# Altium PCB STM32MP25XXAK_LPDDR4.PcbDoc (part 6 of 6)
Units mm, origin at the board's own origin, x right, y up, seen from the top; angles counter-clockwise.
Board outline 120 x 79.6 mm, 4 copper layers (Top Layer, Signal Layer 1, Signal Layer 2, Bottom Layer), stack 1.614 mm thick; 190 components, 143 nets, 1208 pads, 757 vias.
Unrouted connection lines stored in the file: 3.
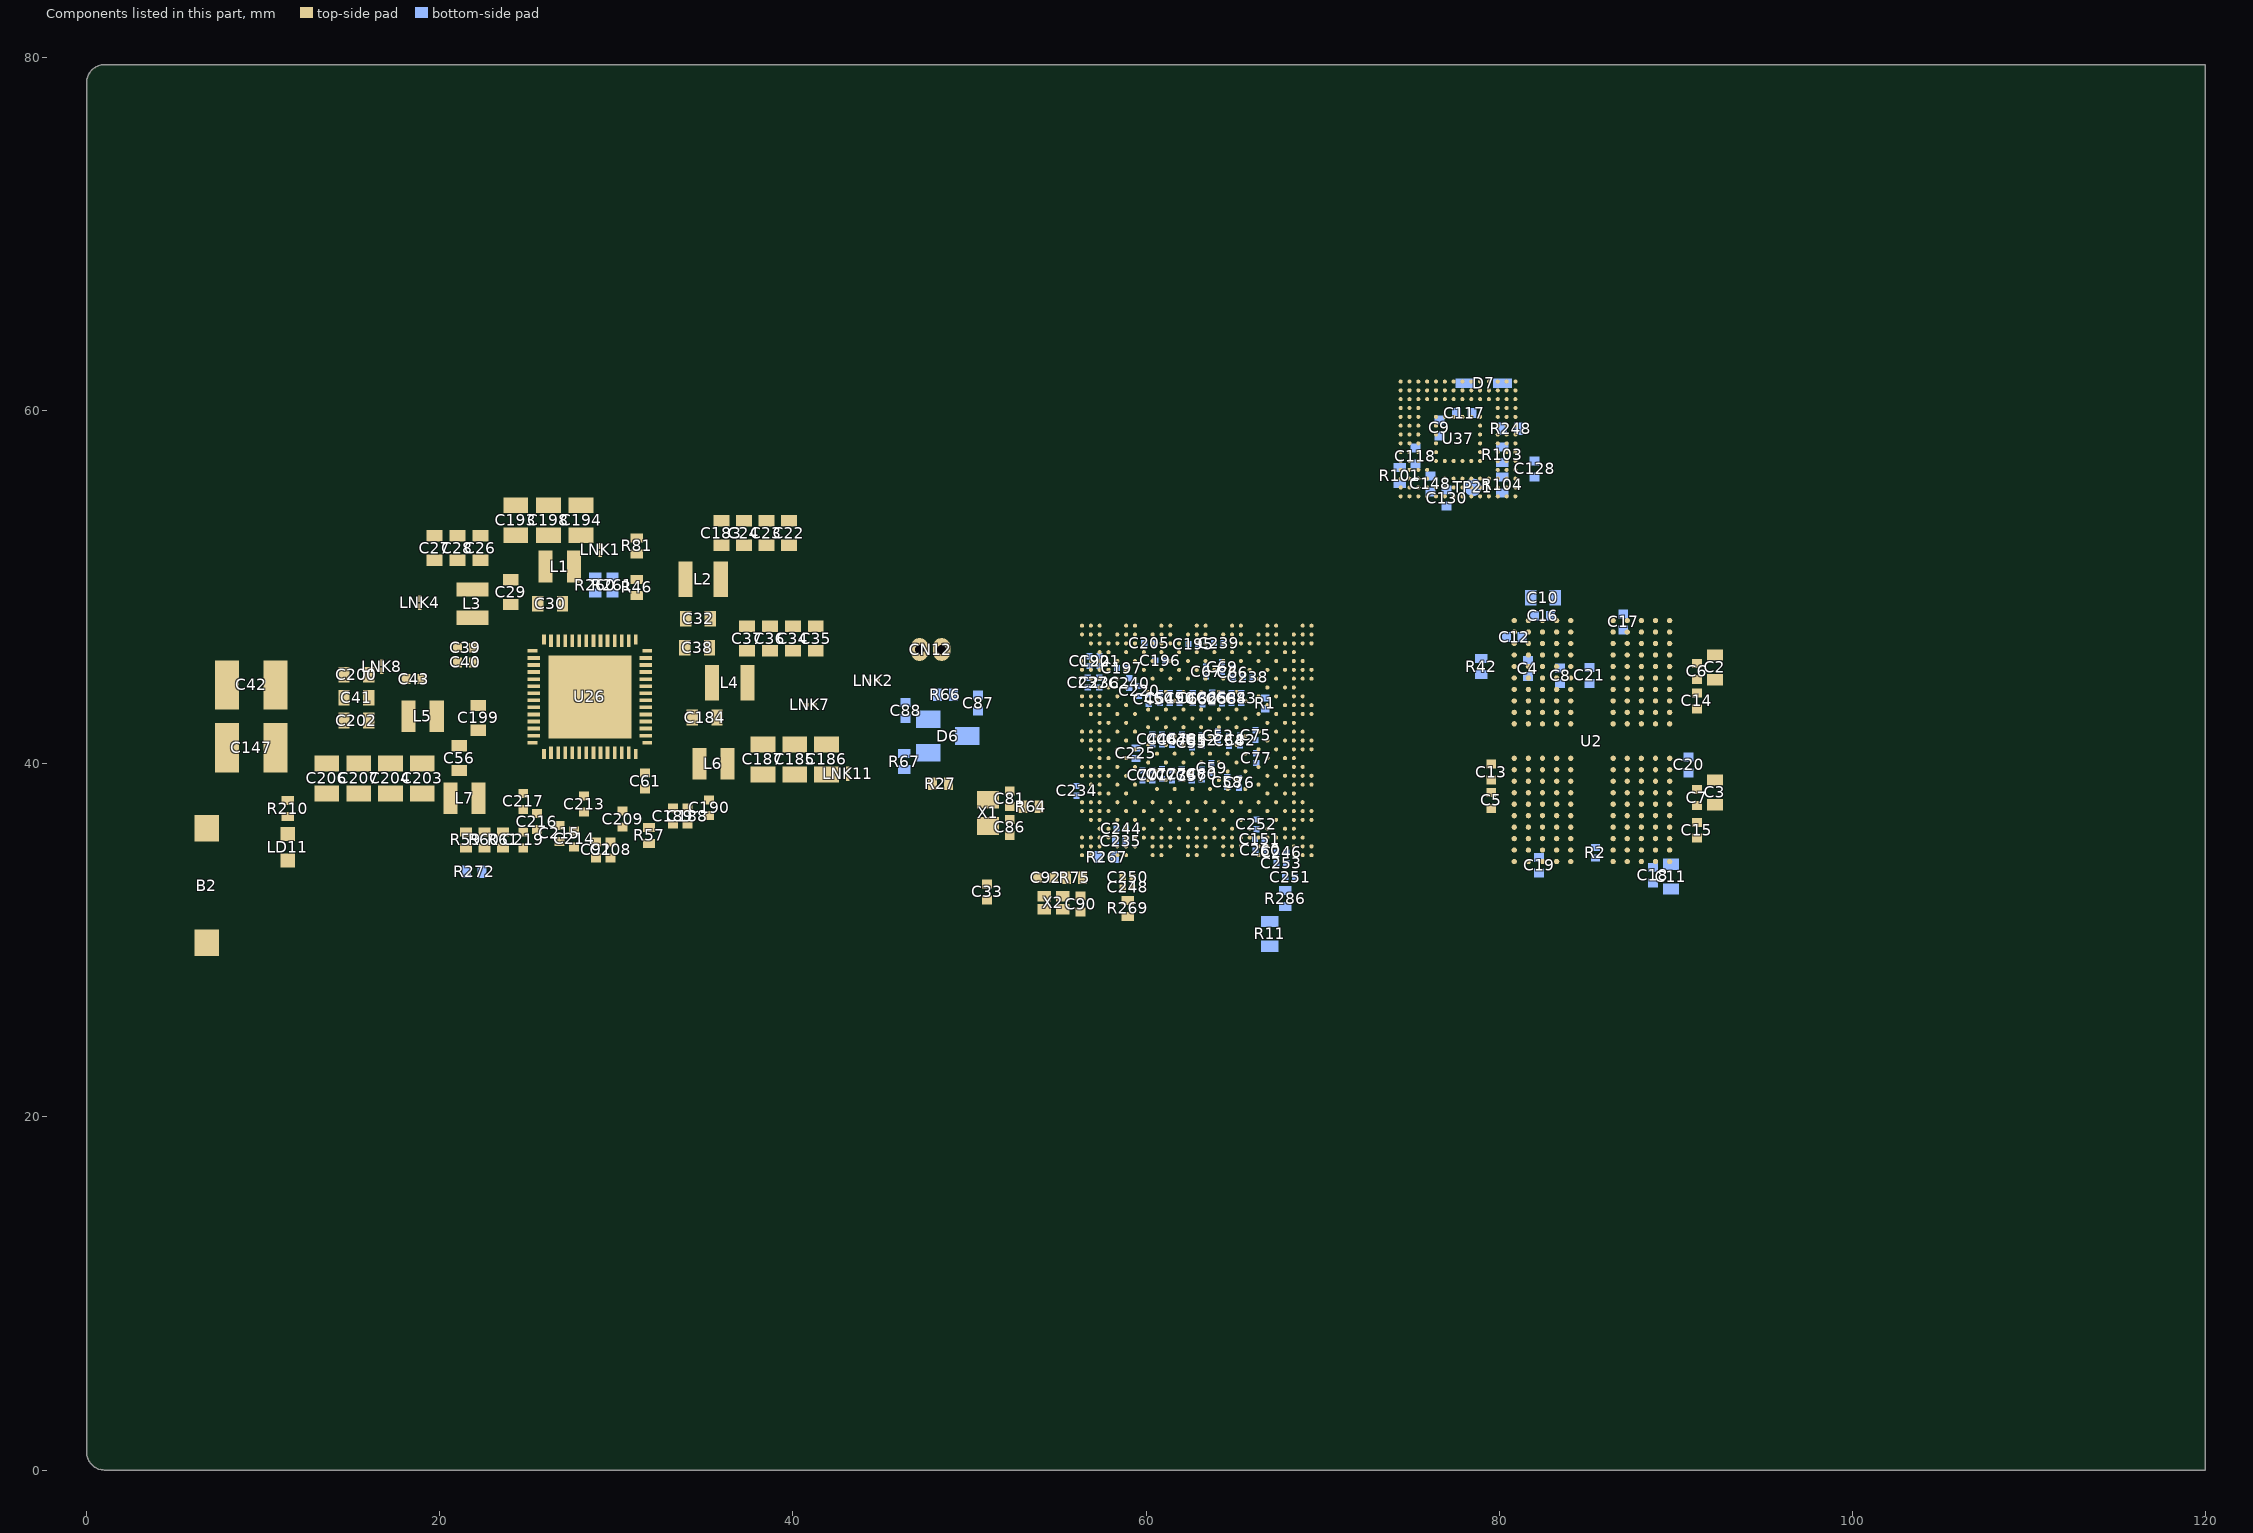
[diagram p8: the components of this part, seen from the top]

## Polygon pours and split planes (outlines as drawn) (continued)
5V_STLK on Signal Layer 2 "5V_STLK_L03_P051" (solid, pour order 51): 11.875,50.635 37.435,50.635 37.475,50.595 37.475,31.99 14.15,31.99 11.911,34.229
GND on Top Layer "GND_L01_P053" (solid, remove dead copper, pour order 53): 0,79.797 120,79.797 120,0.197 0,0.197
5V_STLK on Top Layer "5V_VIN" (solid, pour order 17): 22.51,43.62 23.167,43.62 23.35,43.803 23.35,43.463 22.867,42.98 22.51,42.98
VDDCPU on Top Layer "I_SENS_VDDCPU_P" (solid, pour order 18): 17.812,51.845 17.812,49.998 18.335,49.475 22.75,49.475 22.745,49.48 22.745,51.845
VDDCORE on Top Layer "I_SENS_VDDCORE_P" (solid, pour order 19): 41.007,52.695 43.889,49.813 43.889,43.586 43.894,43.581 42.44,43.581 41.895,44.126 41.895,48.827 41.522,49.2 39.875,49.2 35.515,49.2 35.505,52.695
VDDGPU on Top Layer "I_SENS_VDDGPU_P" (solid, pour order 20): 41.603,43.6 41.745,43.742 41.745,46.72 37.025,46.72 37.025,43.6
VDDIO on Top Layer "VDDIO" (solid, pour order 22): 30.995,46.77 30.995,48.568 31.53,49.103 31.712,49.103 32.15,48.664 32.15,48.123 31.45,47.423 31.45,46.77
3V3 on Top Layer "3V3" (solid, pour order 23): 12.887,36.548 13.062,36.373 19.41,36.373 20.712,37.675 20.712,38.523 13.088,38.523 12.887,38.323
NetL6_1 on Top Layer "NetL13_1" (solid, pour order 25): 33.375,41.863 33.838,41.4 35.1,41.4 35.1,39.1 35.098,39.098 33.801,39.098 33.801,40.722 33.375,41.148
GND on Signal Layer 1 "GND_L02_P000" (solid, remove dead copper, pour order 0): 0,79.6 120,79.6 120,0 0,0
GND on Bottom Layer "GND_L04_P055" (solid, remove dead copper, pour order 55): 0,79.6 120,79.6 120,0 0,0

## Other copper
Top Layer:
  rectangle net VDD2_DDR: 15.655,41.8 18.625,43.6
  region net NetL1_1: 27.572,49.875 ccw(c27.269,49.883) 27.478,50.102 27.455,50.125 27.455,50.187 27.526,50.194 ccw(c27.525,50.194) 27.525,50.195 27.675,50.075
  region net GND: 32.225,44 32.15,43.925 32.072,43.925 cw(c32.072,43.798) 32.162,43.888 32.188,43.862 ccw(c32.278,43.952) 32.278,43.825 32.947,43.825 cw(c32.947,43.698) 33.037,43.788 33.1,43.725 33.229,43.854 cw(c33.28,43.803) 33.28,43.875
  region net 5V_STLK: 33.605,47.78 33.43,47.672 ccw(c33.563,47.473) 33.394,47.642 33.353,47.601 ccw(c33.613,47.342) 33.246,47.342 33.246,47.326 ccw(c33.601,47.326) 33.35,47.075 33.35,45.539 33.349,45.538 33.347,45.551 32.876,45.08 32.27,45.08 32.27,45.345 32.506,45.345 32.98,45.819 32.98,48.347 33.308,48.67 34.325,48.67 34.325,47.78
  region net 5V_STLK: 25.23,48.524 25.131,48.425 24.775,48.425 cw(c24.775,48.775) 24.425,48.775 24.425,48.825 23.7,48.825 ccw(c23.7,48.75) 23.625,48.75 23.625,48.4 ccw(c23.827,48.397) 23.825,48.195 26.45,48.195 26.85,47.8 27.112,47.8 26.391,48.521 26.125,48.525
  region net GND: 24.9,47.685 24.807,47.685 ccw(c24.807,47.584) 24.735,47.655 24.455,47.375 ccw(c24.526,47.303) 24.425,47.303 24.425,46.975 24.925,46.975 cw(c25.323,46.982) 25.315,47.38 25.575,47.375 ccw(c25.575,47.423) 25.609,47.389 25.705,47.485
  pour cut-out: 56.125,47.825 69.49,47.825 69.49,34.475 69.524,34.441 56.137,34.441
  pour cut-out: 67.469,46.428 67.537,46.496 69.625,46.496 74.724,51.594 87.59,51.594 90.709,48.476 90.709,33.404 86.764,29.459 74.76,29.459 67.404,36.815
  pour cut-out: 74.075,62 81.35,62 81.35,54.798 74.075,54.798
  region net GND: 39,41.298 39,42.651 37.6,42.651 37.6,41.298
  region net GND: 40.8,41.298 40.8,42.651 39.4,42.651 39.4,41.298
  region net GND: 42.6,41.298 42.6,42.651 41.2,42.651 41.2,41.298
  region net GND: 36.502,42.375 36.307,42.18 36,42.18 36,43.07 36.475,43.07 36.67,42.875 36.67,42.375
  region net GND: 36.325,47.975 36.13,47.78 35.275,47.78 35.275,48.67 36.13,48.67 36.325,48.475
  region net GND: 24.275,51.373 24.47,51.178 24.47,50.723 23.58,50.723 23.58,51.178 23.775,51.373
  region net GND: 36.3,46.325 36.105,46.13 35.25,46.13 35.25,47.02 36.105,47.02 36.3,46.825
  region net GND: 37.65,48.825 37.845,48.63 37.845,47.775 36.955,47.775 36.955,48.63 37.15,48.825
  region net GND: 38.95,48.825 39.145,48.63 39.145,47.775 38.255,47.775 38.255,48.63 38.45,48.825
  region net GND: 40.25,48.825 40.445,48.63 40.445,47.775 39.555,47.775 39.555,48.63 39.75,48.825
  region net GND: 41.55,48.825 41.745,48.63 41.745,47.775 40.855,47.775 40.855,48.63 41.05,48.825
  region net VDDIO: 41.58,38.835 41.58,38.719 41.227,38.366 41.227,37.235 41.58,37.235 42.22,37.235 42.577,37.235 42.577,38.431 42.22,38.788 42.22,39.212 41.58,39.212
  region net 5V_STLK: 20.075,39.948 20.725,39.948 20.725,39.305 20.42,39.305 20.325,39.4 20.075,39.4
  region net GND: 19.025,40.798 19.175,40.648 19.175,40.398 18.3,40.398 18.3,40.823 18.525,41.048 19.025,41.048
  region net GND: 19.025,40.798 18.875,40.648 18.875,40.398 19.7,40.398 19.7,40.873 19.525,41.048 19.025,41.048
  region net GND: 17.225,40.798 17.375,40.648 17.375,40.398 16.5,40.398 16.5,40.823 16.725,41.048 17.225,41.048
  region net GND: 17.225,40.798 17.075,40.648 17.075,40.398 17.9,40.398 17.9,40.873 17.725,41.048 17.225,41.048
  region net GND: 15.425,40.798 15.575,40.648 15.575,40.398 14.7,40.398 14.7,40.823 14.925,41.048 15.425,41.048
  region net GND: 15.425,40.798 15.275,40.648 15.275,40.398 16.1,40.398 16.1,40.873 15.925,41.048 15.425,41.048
  region net GND: 13.625,40.798 13.775,40.648 13.775,40.398 12.9,40.398 12.9,40.823 13.125,41.048 13.625,41.048
  region net GND: 13.625,40.798 13.475,40.648 13.475,40.398 14.3,40.398 14.3,40.873 14.125,41.048 13.625,41.048
  region net GND: 20.075,40.75 20.12,40.705 20.68,40.705 20.725,40.75 20.725,41.345 20.42,41.345 20.325,41.25 20.075,41.25
  region net 5V_STLK: 23.25,43.62 23.25,43.4 22.83,42.98 21.15,42.98 21.15,43.525 21.4,43.525 21.495,43.62
  region net GND: 21.925,40.952 21.73,41.147 21.73,41.602 22.62,41.602 22.62,41.147 22.425,40.952
  region net 5V_STLK: 27.175,49.85 27.27,49.755 27.27,49.45 26.63,49.45 26.63,49.805 26.675,49.85 26.675,50.1 27.175,50.1
  region net GND: 24.6,49.323 24.797,49.52 25.25,49.52 25.25,48.63 24.793,48.63 24.6,48.823
  region net VDD2_DDR: 16.295,45.615 16.295,45.731 16.648,46.084 16.648,47.215 16.295,47.215 15.655,47.215 15.298,47.215 15.298,46.019 15.655,45.662 15.655,45.238 16.295,45.238
  region net GND: 13.6,42.7 13.795,42.895 14.575,42.895 14.575,42.005 13.795,42.005 13.6,42.2
  region net GND: 13.6,44 13.795,44.195 14.575,44.195 14.575,43.305 13.795,43.305 13.6,43.5
  region net GND: 13.6,45.3 13.795,45.495 14.575,45.495 14.575,44.605 13.795,44.605 13.6,44.8
  region net GND: 22.55,53.873 22.745,53.678 22.745,53.223 21.855,53.223 21.855,53.678 22.05,53.873
  region net GND: 21.25,53.873 21.445,53.678 21.445,53.223 20.555,53.223 20.555,53.678 20.75,53.873
  region net GND: 19.95,53.873 20.145,53.678 20.145,53.223 19.255,53.223 19.255,53.678 19.45,53.873
  region net GND: 40.025,54.825 40.22,54.63 40.22,53.775 39.33,53.775 39.33,54.63 39.525,54.825
  region net GND: 38.75,54.825 38.945,54.63 38.945,53.775 38.055,53.775 38.055,54.63 38.25,54.825
  region net GND: 37.475,54.825 37.67,54.63 37.67,53.775 36.78,53.775 36.78,54.63 36.975,54.825
  region net GND: 36.2,54.825 36.395,54.63 36.395,53.775 35.505,53.775 35.505,54.63 35.7,54.825
  region net GND: 24.325,55.425 24.475,55.275 24.475,55.025 23.6,55.025 23.6,55.45 23.825,55.675 24.325,55.675
  region net GND: 24.325,55.425 24.175,55.275 24.175,55.025 25,55.025 25,55.5 24.825,55.675 24.325,55.675
  region net GND: 26.175,55.425 26.025,55.275 26.025,55.025 26.85,55.025 26.85,55.5 26.675,55.675 26.175,55.675
  region net GND: 26.175,55.425 26.325,55.275 26.325,55.025 25.45,55.025 25.45,55.45 25.675,55.675 26.175,55.675
  region net GND: 28.025,55.425 27.875,55.275 27.875,55.025 28.7,55.025 28.7,55.5 28.525,55.675 28.025,55.675
  region net GND: 28.025,55.425 28.175,55.275 28.175,55.025 27.3,55.025 27.3,55.45 27.525,55.675 28.025,55.675
  region net NetL2_1: 33.65,50.225 33.65,49.45 33.515,49.45 32.825,48.76 32.825,46 32.35,45.525 32.025,45.525 32.025,45.675 32.114,45.675 32.27,45.831 32.45,46.011 32.505,46.094 32.525,46.191 32.525,46.742 32.57,46.85 32.57,47.01 32.509,47.157 32.397,47.269 32.27,47.322 32.25,47.325 32.25,51.102 32.598,51.45 33.515,51.45 33.65,51.315 33.65,51.2
  region net NetL4_1: 34.525,45.6 34.525,43.6 35.434,43.6 35.434,45.6
  region net NetL3_1: 22.575,46.975 21.388,48.162 22.488,48.162 22.575,48.075 26.18,48.075 26.42,47.835 24.79,47.835 24.768,47.833 24.748,47.829 24.72,47.82 24.701,47.813 24.675,47.799 24.658,47.788 24.635,47.769 24.341,47.474 24.322,47.452 24.311,47.435 24.302,47.419 24.29,47.39 24.286,47.378 24.281,47.362 24.277,47.342 24.276,47.327 24.274,47.313 24.274,46.975
  region net NetL3_1: 23.783,48.045 23.754,48.048 23.725,48.057 23.651,48.089 23.625,48.103 23.603,48.122 23.547,48.18 23.528,48.203 23.514,48.229 23.488,48.294 23.481,48.316 23.458,48.347 23.433,48.367 23.397,48.391 23.351,48.4 22.575,48.4 22.575,47.263
  region net NetL7_1: 22.875,38.35 22.575,38.05 21.8,38.05 21.8,38.95 22.875,40.02
  region net NetL1_1: 27.995,50.275 27.65,49.93 27.195,50.385 27.195,52.075 27.995,52.075
  region net NetL5_1: 19.425,43.948 19.65,44.173 21.025,44.173 21.025,42.323 20.502,41.8 20.225,41.8 19.425,41.8
  region net 5V_STLK: 34.125,45.25 33.55,44.675 32.875,44.675 32.875,44.85 33.4,45.375
  region net GND: 32.83,44.125 33.28,44.125 33.28,43.825 33.155,43.7 32.98,43.875 32.83,43.875
  region net 5V_STLK: 34.075,41.85 33.977,41.948 33.977,42.625 34.62,42.625 34.62,41.895 34.575,41.85 34.575,41.6 34.075,41.6
  region net 5V_STLK: 34.075,41.875 34.075,42.125 33.175,43.025 33.925,43.025 34.247,42.703
  region net 5V_STLK: 34.195,46.175 34.195,45.32 34.125,45.25 34,45.375 33.4,45.375 33.555,45.53 33.555,46.175
  pour cut-out: 42.6,39.925 37.63,39.925 37.63,40.575 42.6,40.575
  pour cut-out: 12.9,38.773 19.55,38.773 19.55,39.573 12.9,39.573
  region net 5V_STLK: 34.175,49 34.325,48.85 34.325,48.6 33.525,48.6 33.525,48.85 33.675,49 33.675,49.25 34.175,49.25
  region net 5V_STLK: 23.25,49.3 23.295,49.345 23.65,49.345 23.65,48.65 23.4,48.65 23.25,48.8 23,48.8 23,49.3
  region net GND: 31.921,46.656 32.02,46.656 32.049,46.653 32.078,46.644 32.104,46.63 32.127,46.612 32.145,46.589 32.17,46.555 32.17,46.23 32.27,46.23 32.27,46.93 31.921,46.93
  region net 5V_STLK: 27.425,47.725 27.4,47.725 26.63,48.495 26.63,48.825 27.27,48.825 27.27,48.605 27.4,48.475 27.4,47.925
  region net GND: 25.575,47.375 25.24,47.375 25.24,47.385
  pour cut-out: 35.9,41.075 35.1,41.075 35.1,38.975 35.9,38.975
  pour cut-out: 36.955,45.45 35.895,45.45 35.895,43.35 36.955,43.35
  pour cut-out: 35.445,51.25 34.385,51.25 34.385,49.15 35.445,49.15
  pour cut-out: 21.94,39.1 20.88,39.1 20.88,37 21.94,37
  pour cut-out: 27.155,52.225 26.435,52.225 26.435,50.125 27.155,50.125
  pour cut-out: 20.8,49.605 20.8,48.545 22.9,48.545 22.9,49.605
  pour cut-out: 21.5,40.6 19.55,40.6 19.55,40.025 21.5,40.025
  region net 5V_STLK: 22.875,40.9 22.716,40.9 22.689,40.874 22.648,40.842 22.602,40.815 22.554,40.795 22.503,40.782 22.451,40.775 22.425,40.774 21.925,40.774 21.899,40.775 21.847,40.782 21.796,40.795 21.748,40.815 21.702,40.842 21.661,40.874 21.65,40.45 21.65,39.945 21.375,39.945 21.375,39.305 21.83,39.305 22.599,40.074 22.599,40.184 22.603,40.227 22.613,40.27 22.629,40.31 22.652,40.346 22.68,40.379 23.038,40.737
  pour cut-out: 18.495,41.65 19.555,41.65 19.555,43.75 18.495,43.75
  pour cut-out: 35.855,40.875 37.63,40.875 37.63,39.6 36.3,39.6
  region net 5V_STLK: 34.125,47.35 34.275,47.2 34.275,46.95 33.475,46.95 33.475,47.2 33.625,47.35 33.625,47.6 34.125,47.6
Bottom Layer:
  pour cut-out: 66.146,48.032 66.498,48.032 73.987,48.032 76.358,45.662 88.892,45.662 88.892,38.218 85.406,34.732 68.413,34.732 66.15,36.923

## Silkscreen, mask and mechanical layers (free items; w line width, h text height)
Top Overlay:
  text "J" at 27.263,70.56 h15
Drill Drawing:
  drawing of 190 lines, arcs and shapes, not listed
  text "PCB SPECIFICATIONS :" at -27.02,127.275 h3
  text "A.   MATERIAL :" at -27.02,123.275 h3
  text "FR-4" at 11.48,123.275 h3
  text "TG-170" at 27.98,123.275 h3
  text "X  TG-150" at 46.23,123.275 h3
  text "TG-140" at 62.23,123.275 h3
  text "B.   MATERIAL FAMILY :" at -27.02,120.275 h3
  text "N/A" at 11.48,120.275 h3
  text "C.   SOLDERMASK COLOR :" at -27.02,117.275 h3
  text "GREEN" at 11.48,117.275 h3
  text "X  BLUE" at 27.98,117.275 h3
  text "RED" at 46.23,117.275 h3
  text "BLACK" at 62.23,117.275 h3
  text "D.   SILKSCREEN COLOR :" at -27.02,114.275 h3
  text "X  WHITE" at 11.48,114.275 h3
  text "YELLOW" at 27.98,114.275 h3
  text "BLACK" at 46.23,114.275 h3
  text "PCB : TYPE 4" at 187.138,113.471 h3
  text "Layer" at 122.2,111.475 h2
  text "Name" at 130.564,111.475 h2
  text "Material" at 146.732,111.475 h2
  text "Thickness" at 161.266,111.475 h2
  text "Constant" at 173.202,111.475 h2
  text "E.   SURFACE FINISH :" at -27.02,111.275 h3
  text "X  ENIG" at 11.48,111.275 h3
  text "IMMERSION SILVER" at 27.98,111.275 h3
  text "IMMERSION TIN" at 62.23,111.275 h3
  text "HASL" at 11.48,108.275 h3
  text "HASL (PB-FREE)" at 27.98,108.275 h3
  text "GOLDEN FINGER" at 62.23,108.275 h3
  text "ASPECT-RATIO, AXE Z :" at 187.138,107.971 h3
  text "Top Overlay" at 130.564,107.475 h2
  text "F.   IMPEDANCE CONTROL :" at -27.02,105.275 h3
  text "NO" at 11.48,105.275 h3
  text "X  YES" at 27.98,105.275 h3
  text "Top Solder" at 130.564,103.475 h2
  text "Solder Resist" at 146.732,103.475 h2
  text "0.025mm" at 161.266,103.475 h2
  text "3.5" at 173.202,103.475 h2
  text "G.   THROUGH VIA :" at -27.02,102.275 h3
  text "PLUG THE VIAS WHICH ARE COVERED WITH SOLDERMASK ONE OR TWO SIDE." at 11.48,102.275 h3
  text "6 :1  to  8 :1 / LEVEL \"B\"" at 187.157,101.224 h3
  text "1" at 122.2,99.475 h2
  text "Top Layer" at 130.564,99.475 h2
  text "0.037mm" at 161.266,99.475 h2
  text "PLUG MATERIAL :" at 11.48,99.275 h3
  text "X  SOLDERMASK" at 36.98,99.275 h3
  text "NON-CONDUCTIVE EPOXY." at 62.23,99.275 h3
  text "H.   STACK-UP :" at -27.02,96.275 h3
  text "SEE LAYER STACK-UP SEQUENCE FOR OVERALL THICKNESS." at 11.48,96.275 h3
  text "Dielectric 1" at 130.564,95.475 h2
  text "0.070mm" at 161.266,95.475 h2
  text "3.8" at 173.202,95.475 h2
  text "2" at 122.198,91.475 h2
  text "Signal Layer 1" at 130.564,91.475 h2
  text "0.035mm" at 161.266,91.475 h2
  text "MINIMUN PARAMETERS" at 187.25,89.695 h3
  text "Dielectric 2" at 130.564,87.475 h2
  text "1.330mm" at 161.266,87.475 h2
  text "4.3" at 173.202,87.475 h2
  text "DEFAULT" at 187.25,84.195 h3
  text "3" at 122.2,83.475 h2
  text "Signal Layer 2" at 130.564,83.475 h2
  text "0.035mm" at 161.266,83.475 h2
  text "Dielectric 3" at 130.564,79.475 h2
  text "0.070mm" at 161.266,79.475 h2
  text "3.8" at 173.202,79.475 h2
  text "TRACKS : 0.100mm           / GAPS : 0.100mm" at 187.25,78.445 h3
  text "4" at 122.2,75.475 h2
  text "Bottom Layer" at 130.564,75.475 h2
  text "0.037mm" at 161.266,75.475 h2
  text "BGA :" at 187.225,73.62 h3
  text "Bottom Solder" at 130.564,71.475 h2
  text "Solder Resist" at 146.732,71.475 h2
  text "0.025mm" at 161.266,71.475 h2
  text "3.5" at 173.202,71.475 h2
  text "TRACKS : 0.090mm           / GAPS : 0.090mm" at 187.225,67.87 h3
  text "Bottom Overlay" at 130.564,67.475 h2
  text "Symbol" at 108.265,-14.395 h2.4
  text "Count" at 117.653,-14.395 h2.4
  text "Hole Size" at 127.378,-14.395 h2.4
  text "Plated" at 138.78,-14.395 h2.4
  text "Hole Type" at 147.023,-14.395 h2.4
  text "Drill Layer Pair" at 159.023,-14.395 h2.4
  text "Via/Pad" at 181.752,-14.395 h2.4
  text "Pad Shape" at 191.584,-14.395 h2.4
  text "Hole Length" at 204.429,-14.395 h2.4
  text "480" at 117.653,-18.533 h2
  text "0.200mm" at 127.378,-18.533 h2
  text "PTH" at 138.78,-18.533 h2
  text "Round" at 147.023,-18.533 h2
  text "Top Layer - Bottom Layer" at 159.023,-18.533 h2
  text "Via" at 181.752,-18.533 h2
  text "Rounded" at 191.584,-18.533 h2
  text "-" at 204.429,-18.533 h2
  text "D" at 107.477,-18.786 h1.84
  text "277" at 117.653,-22.67 h2
  text "0.350mm" at 127.378,-22.67 h2
  text "PTH" at 138.78,-22.67 h2
  text "Round" at 147.023,-22.67 h2
  text "Top Layer - Bottom Layer" at 159.023,-22.67 h2
  text "Via" at 181.752,-22.67 h2
  text "Rounded" at 191.584,-22.67 h2
  text "-" at 204.429,-22.67 h2
  text "C" at 107.477,-22.924 h1.84
  text "2" at 117.653,-26.807 h2
  text "0.500mm" at 127.378,-26.807 h2
  text "PTH" at 138.78,-26.807 h2
  text "Round" at 147.023,-26.807 h2
  text "Top Layer - Bottom Layer" at 159.023,-26.807 h2
  text "Pad" at 181.752,-26.807 h2
  text "Rounded" at 191.584,-26.807 h2
  text "-" at 204.429,-26.807 h2
  text "759 Total" at 117.653,-30.945 h2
